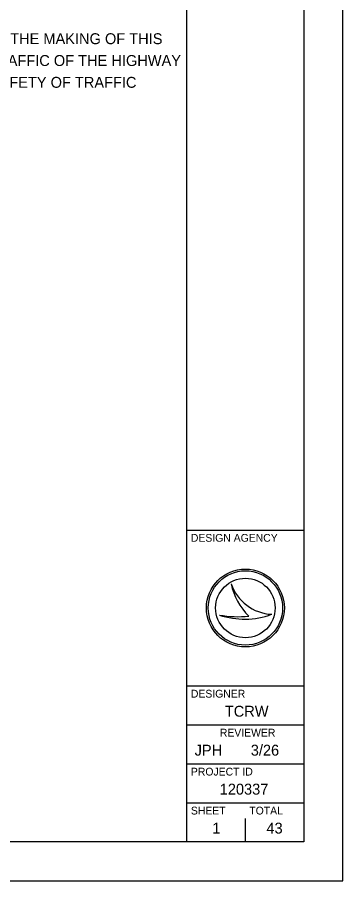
# Model space of a CAD drawing. Extents: x 0 to 34, y 0 to 22.
# Drawn here: x 29.82 to 34, y 0 to 11.08 of the extents above; entities that cross this region are included whole.
import ezdxf

# ---------------------------------------------------------------- set-up
doc = ezdxf.new("R2010")
doc.units = 0
for name, color, linetype in [('SH_Border', 7, 'Continuous'), ('SH_Cut_Line', 7, 'Continuous'), ('SH_Data', 7, 'Continuous')]:
    doc.layers.add(name, color=color, linetype=linetype)

msp = doc.modelspace()

# ---------------------------------------------------------------- linework, layer by layer
at = {"layer": 'SH_Border'}
for p, q in [((32, 0.5), (32, 21.5)), ((32, 4.5), (33.5, 4.5)), ((32, 2.5), (33.5, 2.5)), ((32, 2), (33.5, 2)), ((32, 1.5), (33.5, 1.5)), ((32, 1), (33.5, 1))]:
    msp.add_line(p, q, dxfattribs=at)
msp.add_lwpolyline([(1.5, 21.5), (33.5, 21.5), (33.5, 0.5), (1.5, 0.5)], close=True, dxfattribs=at)
at = {"layer": 'SH_Cut_Line'}
msp.add_lwpolyline([(0, 0), (34, 0), (34, 22), (0, 22)], close=True, dxfattribs=at)
at = {"layer": 'SH_Data'}
for p, q in [((32.567, 3.81), (32.567, 3.81)), ((32.75, 3.5), (32.75, 3.5)), ((32.417, 3.41), (32.417, 3.41)), ((33.087, 3.419), (33.087, 3.419)), ((32.75, 0.5), (32.75, 0.8)), ((32.375, 0.675), (32.375, 0.675))]:
    msp.add_line(p, q, dxfattribs=at)
for radius in [0.5, 0.477, 0.477, 0.382]:
    msp.add_circle((32.75, 3.5), radius, dxfattribs=at)
for centre, radius, start, end in [((33.116, 3.998), 0.58, 198.9257, 198.9319), ((33.347, 3.97), 0.796, 191.6379, 191.6421), ((33.116, 3.998), 0.58, 198.9319, 267.1657), ((33.347, 3.97), 0.796, 191.6421, 226.0947), ((32.739, 4.37), 1.013, 251.4576, 290.0832), ((32.648, 4.654), 1.266, 259.4964, 259.4995), ((32.739, 4.37), 1.013, 251.4527, 251.4576), ((32.648, 4.654), 1.266, 259.4995, 276.6672)]:
    msp.add_arc(centre, radius, start, end, dxfattribs=at)

# ---------------------------------------------------------------- texts
for s, height, p in [(' I HEREBY APPROVE THESE PLANS AND DECLARE THAT THE MAKING OF THIS', 0.14, (24.528, 10.735)), ('IMPROVEMENT WILL NOT REQUIRE THE CLOSING TO TRAFFIC OF THE HIGHWAY', 0.14, (24.528, 10.455)), ('AND THAT PROVISIONS FOR THE MAINTENANCE AND SAFETY OF TRAFFIC', 0.14, (24.528, 10.175)), ('DESIGN AGENCY', 0.1, (32.05, 4.35)), ('DESIGNER', 0.1, (32.05, 2.35)), ('TCRW', 0.14, (32.486, 2.105)), ('REVIEWER', 0.1, (32.422, 1.85)), ('JPH', 0.14, (32.098, 1.605)), ('3/26', 0.14, (32.819, 1.605)), ('PROJECT ID', 0.1, (32.05, 1.35)), ('120337', 0.14, (32.42, 1.105)), ('SHEET', 0.1, (32.05, 0.85)), ('TOTAL', 0.1, (32.8, 0.85)), ('1', 0.14, (32.325, 0.605)), ('43', 0.14, (33.02, 0.605))]:
    msp.add_text(s, height=height, dxfattribs=at).set_placement(p)

doc.saveas('drawing.dxf')
